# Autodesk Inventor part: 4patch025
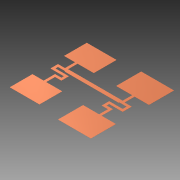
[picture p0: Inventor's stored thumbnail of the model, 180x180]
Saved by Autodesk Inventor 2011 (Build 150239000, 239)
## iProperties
Created: 2014-03
Part Number: 4patch025
Document SubType Name: Modeling
Designer: Evgeny
Density: 1 g/cm^3
Author: Evgeny
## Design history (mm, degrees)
sketch "Эскиз1"
  geometry: L1 (-65, 4.5)-(64.5, 4.5); L2 (64.5, -3)-(64.5, -4.5); L3 (64.5, -4.5)-(-64.5, -4.5); L4 (-64.5, -4.5)-(-64.5, -3); L5 (-71, 3)-(-81.5, 3); L6 (-81.5, -3)-(-64.5, -3); L7 (-71, 3)-(-71, 27); L8 (-71, 27)-(-65, 27); L9 (-65, 27)-(-65, 4.5); L10 (-81.5, 3)-(-87.5, 3); L11 (-87.5, 3)-(-87.5, -14); L12 (-81.5, -9)-(-81.5, -3); L13 (-81.5, -9)-(-49.5, -9); L14 (-49.5, -9)-(-49.5, -25); L15 (-55.5, -15)-(-87.5, -15); L16 (-87.5, -15)-(-87.5, -14); L17 (-55.5, -15)-(-55.5, -21); L18 (-56.5, -27)-(-49.5, -27); L19 (-49.5, -27)-(-49.5, -25); L20 (-56.5, -27)-(-64.5, -27); L21 (-70.5, -37)-(-70.5, -21); L22 (-70.5, -21)-(-55.5, -21); L23 (-70.5, -21)-(-66, -21); L24 (-64.5, -27)-(-64.5, -48); L25 (-64.5, -48)-(-70.5, -48); L26 (-70.5, -48)-(-70.5, -21); L27 (70.5, 3)-(87.5, 3); L28 (87.5, 3)-(87.5, -3); L29 (81.5, -3)-(64.5, -3); L30 (70.5, 3)-(70.5, 27); L31 (70.5, 27)-(64.5, 27); L32 (64.5, 27)-(64.5, 4.5); L33 (81.5, -3)-(81.5, -12.5); L34 (85.5, -18.5)-(87.5, -18.5); L35 (87.5, -18.5)-(87.5, -3); L36 (85.5, -18.5)-(55.5, -18.5); L37 (49.5, -15)-(49.5, -12.5); L38 (49.5, -12.5)-(81.5, -12.5); L39 (49.5, -12.5)-(55.5, -12.5); L40 (55.5, -18.5)-(55.5, -24.5); L41 (55.5, -30.5)-(49.5, -30.5); L42 (49.5, -30.5)-(49.5, -12.5); L43 (55.5, -30.5)-(64.5, -30.5); L44 (70.5, -27)-(70.5, -24.5); L45 (70.5, -24.5)-(55.5, -24.5); L46 (70.5, -24.5)-(65, -24.5); L47 (64.5, -30.5)-(64.5, -51.5); L48 (64.5, -51.5)-(70.5, -51.5); L49 (70.5, -51.5)-(70.5, -24.5); L50 (-97.1, 81)-(-26.5, 81); L51 (-26.5, 81)-(-26.5, 27); L52 (-26.5, 27)-(-97.1, 27); L53 (-97.1, 27)-(-97.1, 81); L54 (26.5, 86.5)-(104.5, 86.5); L55 (104.5, 86.5)-(104.5, 27); L56 (104.5, 27)-(26.5, 27); L57 (26.5, 27)-(26.5, 86.5); L58 (-97.1, -102)-(-26.5, -102); L59 (-26.5, -102)-(-26.5, -48); L60 (-26.5, -48)-(-97.1, -48); L61 (-97.1, -48)-(-97.1, -102); L62 (26.5, -111)-(104.5, -111); L63 (104.5, -111)-(104.5, -51.5); L64 (104.5, -51.5)-(26.5, -51.5)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; 1 further point
  constraints: 130 end point, 28 parallel, 15 horizontal, 14 perpendicular
  dimensions: "d0" = 129 distance between parallel lines of L2 L4; "d1" = 64.5 distance from line of point (0, 0) L4; "d2" = 9 distance between parallel lines of L3 L1; "d3" = 4.5 distance from line of point (0, 0) L3; "d5" = 6 distance between parallel lines of L5 L6; "d6" = 22.5 distance between parallel lines of L8 L1; "d7" = 6 distance between parallel lines of L7 L9; "d8" = 17 distance from line of L4.end L12; "d9" = 6 distance between parallel lines of L11 L12; "d10" = 6 distance between parallel lines of L13 L6; "d11" = 6 distance between parallel lines of L15 L13; "d12" = 15 distance between parallel lines of L19 L24; "d13" = 6 distance between parallel lines of L19 L17; "d14" = 6 distance between parallel lines of L20 L22; "d15" = 6 distance between parallel lines of L26 L24; "d16" = 27 distance between parallel lines of L25 L22; "d17" = 33 distance between parallel lines of L15 L25; "d18" = 64.5 distance from line of L24 point (0, 0); "d19" = 6 distance between parallel lines of L30 L32; "d20" = 17 distance between parallel lines of L33 L2; "d21" = 6 distance between parallel lines of L27 L29; "d22" = 6 distance between parallel lines of L35 L33; "d23" = 6 distance between parallel lines of L36 L38; "d24" = 6 distance between parallel lines of L49 L47; "d25" = 6 distance between parallel lines of L43 L45; "d26" = 6 distance between parallel lines of L42 L40; "d27" = 129 distance between parallel lines of L47 L24; "d28" = 15 distance between parallel lines of L42 L47; "d29" = 33 distance between parallel lines of L36 L48; "d30" = 27 distance between parallel lines of L45 L48; "d31" = 70.6 distance between parallel lines of L53 L51; "d32" = 54 distance between parallel lines of L52 L50; "d33" = 78 distance between parallel lines of L55 L57; "d34" = 59.5 distance between parallel lines of L56 L54; "d35" = 53 distance between parallel lines of L57 L51; "d36" = 26.5 distance from line of L57 point (0, 0); "d37" = 54 distance between parallel lines of L58 L60; "d38" = 70.6 distance between parallel lines of L59 L61; "d39" = 59.5 distance between parallel lines of L62 L64; "d40" = 78 distance between parallel lines of L63 L65; "d41" = 53 distance between parallel lines of L65 L59; "d42" = 26.5 distance from line of L59 point (0, 0); "d45" = 33 distance between parallel lines of L60 L15; "d46" = 33 distance between parallel lines of L64 L36
extrude "Выдавливание1" new body sketch "Эскиз1" distance "d43" = 0.25; taper "d44" = 0 deg
node "Твердое тело1"
